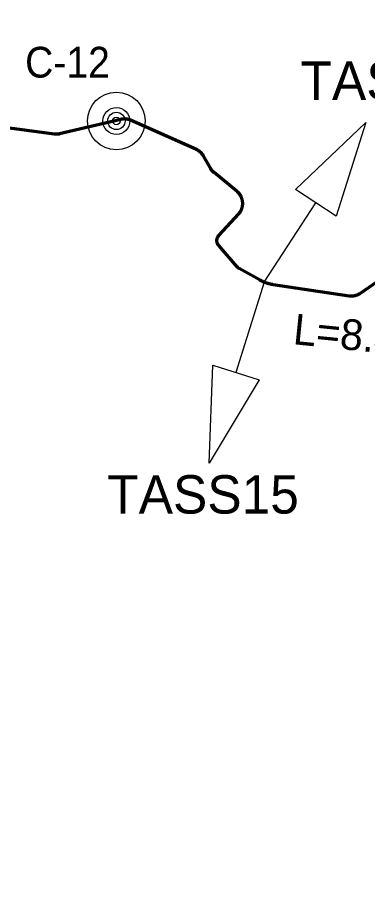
# Model space of a CAD drawing. Extents: x -1643653 to 4543381, y 1624270 to 13878484.
# Drawn here: x 655421 to 659966, y 8945036 to 8956510 of the extents above; entities that cross this region are included whole.
import ezdxf
from ezdxf.enums import TextEntityAlignment as Align

# ---------------------------------------------------------------- set-up
doc = ezdxf.new("R2010")
doc.units = 0
doc.header["$LTSCALE"] = 160
for name, color, linetype, lineweight in [('15', 7, 'Continuous', 25), ('50', 7, 'Continuous', 13), ('54', 7, 'Continuous', 25), ('60', 7, 'Continuous', 13), ('61', 7, 'Continuous', 70)]:
    doc.layers.add(name, color=color, linetype=linetype, lineweight=lineweight)

msp = doc.modelspace()

# ---------------------------------------------------------------- linework, layer by layer
at = {"layer": '15'}
for radius in [375, 175, 112.5, 50]:
    msp.add_circle((656704.4, 8955165.7), radius, dxfattribs=at)
at = {"layer": '54'}
for q in [(659295.8, 8954100.2), (658258.8, 8951892.1)]:
    msp.add_line((658626.7, 8953066.9), q, dxfattribs=at)
for points in [[(659030.8, 8954271.9), (659946.3, 8955145.7), (659560.9, 8953928.6)], [(658560.1, 8951797.7), (657912.1, 8950710.6), (657957.4, 8951986.4)]]:
    msp.add_lwpolyline(points, close=True, dxfattribs=at)
at = {"layer": '60', "lineweight": 25}
msp.add_spline([(814781, 9009175.5), (814787.2, 9009173.4), (814796.9, 9009173.4), (814799.4, 9009172.4), (814805.1, 9009174.5), (814805.6, 9009176.5), (814811.7, 9009179.5), (814811.7, 9009179.5), (814801.5, 9009181), (814790.7, 9009181.5), (814784.1, 9009183.1), (814777.4, 9009185.1), (814778.4, 9009175.5)], degree=3, dxfattribs=at)
at = {"layer": '61'}
for points in [[(657820.9, 8954732.4), (657818.4, 8954735.5), (657815.9, 8954738.6), (657813.3, 8954741.7), (657810.7, 8954744.7), (657808, 8954747.6), (657805.2, 8954750.5), (657802.4, 8954753.3), (657799.5, 8954756.1), (657796.6, 8954758.8), (657793.6, 8954761.5), (657790.6, 8954764.1), (657787.5, 8954766.6), (657784.3, 8954769.1), (657781.1, 8954771.5), (657777.9, 8954773.9), (657774.6, 8954776.2), (657771.3, 8954778.4), (657767.9, 8954780.5), (657764.5, 8954782.6), (657761, 8954784.6), (657757.5, 8954786.6), (657754, 8954788.4), (657750.4, 8954790.2), (657746.8, 8954792), (657743.4, 8954793.5), (656888.7, 8955174), (656885, 8955175.6), (656881.3, 8955177.1), (656877.6, 8955178.6), (656873.8, 8955179.9), (656870, 8955181.2), (656866.2, 8955182.4), (656862.4, 8955183.6), (656858.5, 8955184.6), (656854.6, 8955185.6), (656850.7, 8955186.5), (656846.8, 8955187.4), (656842.9, 8955188.1), (656839, 8955188.8), (656835, 8955189.4), (656831, 8955189.9), (656827.1, 8955190.3), (656823.1, 8955190.7), (656819.1, 8955191), (656815.1, 8955191.2), (656811.1, 8955191.3), (656807.1, 8955191.3), (656803.1, 8955191.2), (656799.1, 8955191.1), (656795.1, 8955190.9), (656791.1, 8955190.6), (656787.1, 8955190.3), (656783.2, 8955189.8), (656779.2, 8955189.3), (656775.2, 8955188.7), (656771.3, 8955188), (656767.4, 8955187.3), (656763.5, 8955186.4), (656761.1, 8955185.9), (655967.1, 8954997.2), (655963.2, 8954996.3), (655959.3, 8954995.5), (655955.4, 8954994.8), (655951.4, 8954994.1), (655947.5, 8954993.6), (655943.5, 8954993.1), (655939.5, 8954992.6), (655935.5, 8954992.3), (655931.6, 8954992.1), (655927.6, 8954991.9), (655923.6, 8954991.8), (655919.6, 8954991.8), (655915.6, 8954991.8), (655911.6, 8954992), (655907.6, 8954992.2), (655903.6, 8954992.5), (655899.6, 8954992.9), (655895.6, 8954993.4), (655894.3, 8954993.6), (654825.8, 8955137.1)], [(658317.7, 8953988.2), (658319.7, 8953991.6), (658321.7, 8953995.1), (658323.6, 8953998.6), (658325.4, 8954002.2), (658327.2, 8954005.8), (658328.8, 8954009.4), (658330.4, 8954013.1), (658332, 8954016.8), (658333.4, 8954020.5), (658334.8, 8954024.2), (658336.1, 8954028), (658337.3, 8954031.8), (658338.5, 8954035.7), (658339.6, 8954039.5), (658340.6, 8954043.4), (658341.5, 8954047.3), (658342.3, 8954051.2), (658343.1, 8954055.1), (658343.8, 8954059.1), (658344.4, 8954063), (658344.9, 8954067), (658345.4, 8954071), (658345.7, 8954074.9), (658346, 8954078.9), (658346.2, 8954082.9), (658346.4, 8954086.9), (658346.4, 8954090.9), (658346.4, 8954094.9), (658346.3, 8954098.9), (658346.1, 8954102.9), (658345.8, 8954106.9), (658345.5, 8954110.9), (658345, 8954114.9), (658344.5, 8954118.8), (658343.9, 8954122.8), (658343.3, 8954126.7), (658342.5, 8954130.7), (658341.7, 8954134.6), (658340.8, 8954138.5), (658339.8, 8954142.3), (658338.8, 8954146.2), (658337.6, 8954150.1), (658336.4, 8954153.9), (658335.1, 8954157.7), (658333.8, 8954161.4), (658332.3, 8954165.1), (658330.8, 8954168.8), (658329.2, 8954172.5), (658327.6, 8954176.2), (658325.8, 8954179.8), (658324, 8954183.3), (658322.2, 8954186.9), (658320.2, 8954190.4), (658318.2, 8954193.8), (658316.1, 8954197.2), (658314, 8954200.6), (658311.8, 8954203.9), (658309.5, 8954207.2), (658307.1, 8954210.5), (658304.7, 8954213.7), (658302.2, 8954216.8), (658299.7, 8954219.9), (658297.1, 8954222.9), (658294.4, 8954225.9), (658291.7, 8954228.8), (658288.9, 8954231.7), (658286.1, 8954234.5), (658283.2, 8954237.3), (658280.3, 8954240), (658277.3, 8954242.7), (658274.2, 8954245.2), (658273.7, 8954245.7), (657973, 8954493.8), (657969.9, 8954496.3), (657966.9, 8954499), (657964, 8954501.7), (657961.1, 8954504.4), (657958.2, 8954507.2), (657955.5, 8954510.1), (657952.7, 8954513), (657950.1, 8954516), (657947.4, 8954519), (657944.9, 8954522.1), (657942.4, 8954525.3), (657940, 8954528.4), (657937.6, 8954531.7), (657935.3, 8954535), (657933.1, 8954538.3), (657930.9, 8954541.6), (657928.8, 8954545), (657926.8, 8954548.5), (657926.1, 8954549.8), (657836.3, 8954709), (657834.3, 8954712.5), (657832.2, 8954715.9), (657830.1, 8954719.3), (657827.9, 8954722.6), (657825.6, 8954725.9), (657823.3, 8954729.2), (657820.9, 8954732.4)], [(658698.8, 8953043.5), (658692.7, 8953045), (658686.6, 8953046.6), (658680.5, 8953048.3), (658674.4, 8953050.1), (658668.3, 8953051.9), (658662.3, 8953053.8), (658656.3, 8953055.8), (658650.3, 8953057.9), (658644.4, 8953060), (658638.5, 8953062.2), (658632.6, 8953064.5), (658626.7, 8953066.9), (658620.9, 8953069.3), (658615.1, 8953071.8), (658609.3, 8953074.4), (658603.6, 8953077.1), (658597.8, 8953079.8), (658592.2, 8953082.6), (658586.5, 8953085.5), (658581, 8953088.4), (658575.4, 8953091.5), (658571.5, 8953093.6), (658301.6, 8953245.4), (658299.2, 8953246.9), (658296.8, 8953248.3), (658294.4, 8953249.9), (658292.1, 8953251.5), (658289.8, 8953253.2), (658287.6, 8953255), (658285.4, 8953256.8), (658283.3, 8953258.7), (658281.2, 8953260.6), (658279.2, 8953262.6), (658277.3, 8953264.6), (658275.4, 8953266.7), (658275.2, 8953267), (658035.3, 8953543.2), (658033.5, 8953545.4), (658031.7, 8953547.6), (658030, 8953549.8), (658028.3, 8953552.2), (658026.8, 8953554.5), (658025.3, 8953556.9), (658023.8, 8953559.3), (658022.5, 8953561.8), (658021.2, 8953564.3), (658020, 8953566.9), (658018.8, 8953569.5), (658017.8, 8953572.1), (658016.8, 8953574.7), (658015.8, 8953577.4), (658015, 8953580.1), (658014.2, 8953582.8), (658013.5, 8953585.6), (658012.9, 8953588.3), (658012.3, 8953591.1), (658011.9, 8953593.9), (658011.5, 8953596.7), (658011.2, 8953599.5), (658011, 8953602.3), (658010.8, 8953605.2), (658010.8, 8953608), (658010.8, 8953610.8), (658010.9, 8953613.6), (658011.1, 8953616.5), (658011.3, 8953619.3), (658011.7, 8953622.1), (658012.1, 8953624.9), (658012.6, 8953627.7), (658013.1, 8953630.4), (658013.8, 8953633.2), (658014.5, 8953635.9), (658015.3, 8953638.6), (658016.2, 8953641.3), (658017.2, 8953644), (658018.2, 8953646.6), (658019.3, 8953649.2), (658020.5, 8953651.8), (658021.7, 8953654.3), (658023.1, 8953656.8), (658024.5, 8953659.3), (658025.9, 8953661.7), (658027.5, 8953664.1), (658029.1, 8953666.4), (658030.7, 8953668.7), (658032.4, 8953671), (658034.2, 8953673.1), (658036.1, 8953675.3), (658037.1, 8953676.4), (658293.8, 8953956.2), (658296.5, 8953959.2), (658299.1, 8953962.2), (658301.6, 8953965.3), (658304.1, 8953968.4), (658306.6, 8953971.6), (658308.9, 8953974.8), (658311.2, 8953978.1), (658313.5, 8953981.4), (658315.6, 8953984.8), (658317.7, 8953988.2)], [(660208.9, 8953156.1), (659872.4, 8952920.6), (659869.1, 8952918.3), (659865.8, 8952916.2), (659862.4, 8952914), (659859, 8952912), (659855.5, 8952910), (659852, 8952908.1), (659848.5, 8952906.2), (659844.9, 8952904.4), (659841.2, 8952902.7), (659837.6, 8952901.1), (659833.9, 8952899.5), (659830.2, 8952898), (659826.5, 8952896.6), (659822.7, 8952895.3), (659818.9, 8952894), (659815.1, 8952892.8), (659811.2, 8952891.7), (659807.4, 8952890.7), (659803.5, 8952889.8), (659799.6, 8952888.9), (659795.7, 8952888.1), (659791.7, 8952887.4), (659787.8, 8952886.7), (659783.8, 8952886.2), (659779.8, 8952885.7), (659775.9, 8952885.3), (659771.9, 8952885), (659767.9, 8952884.7), (659763.9, 8952884.6), (659759.9, 8952884.5), (659755.9, 8952884.5), (659751.9, 8952884.6), (659747.9, 8952884.7), (659743.9, 8952885), (659739.9, 8952885.3), (659735.9, 8952885.7), (659732, 8952886.1), (659728, 8952886.7), (658742.2, 8953035), (658736, 8953036), (658729.8, 8953037), (658723.6, 8953038.2), (658717.3, 8953039.4), (658711.2, 8953040.7), (658705, 8953042), (658698.8, 8953043.5)]]:
    msp.add_lwpolyline(points, dxfattribs=at)

# ---------------------------------------------------------------- texts
at = {"layer": '15', "width": 0.95}
msp.add_text('C-12', height=400, dxfattribs=at).set_placement((655518, 8955730.2))
at = {"layer": '50'}
msp.add_text('L=8.460 m', height=400, rotation=354.202, dxfattribs=at).set_placement((658989.9, 8952261.9))
at = {"layer": '54'}
for s, p in [('TASS16', (660342.6, 8955439.4)), ('TASS15', (657830.5, 8950056))]:
    msp.add_text(s, height=500, dxfattribs=at).set_placement(p, align=Align.CENTER)

doc.saveas('drawing.dxf')
